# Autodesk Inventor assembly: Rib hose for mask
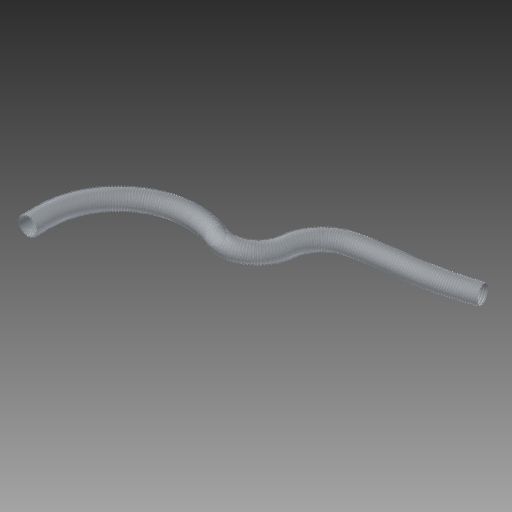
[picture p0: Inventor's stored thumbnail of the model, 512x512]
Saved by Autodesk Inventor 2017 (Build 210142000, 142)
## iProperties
Created: 2020-03
Part Number: Rib hose for mask
Document SubType Name: Assembly
Designer: user
Author: user
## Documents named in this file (3)
- C:\Users\user\Documents\Inventor\Home Ventilator CPAP\Rib hose for mask.iam
- C:\Users\user\Documents\Inventor\Home Ventilator CPAP\hose for mask.ipt
- C:\Users\user\Documents\Inventor\Home Ventilator CPAP\Ring for hose.ipt
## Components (181 placed, 2 different names)
1. hose for mask:1 — Mate:1, Angle:1
2. Ring for hose:1 — Mate:1, Angle:1
3. Ring for hose:2
4. Ring for hose:3
5. Ring for hose:4
6. Ring for hose:5
7. Ring for hose:6
8. Ring for hose:7
9. Ring for hose:8
10. Ring for hose:9
11. Ring for hose:10
12. Ring for hose:11
13. Ring for hose:12
14. Ring for hose:13
15. Ring for hose:14
16. Ring for hose:15
17. Ring for hose:16
18. Ring for hose:17
19. Ring for hose:18
20. Ring for hose:19
21. Ring for hose:20
22. Ring for hose:21
23. Ring for hose:22
24. Ring for hose:23
25. Ring for hose:24
26. Ring for hose:25
27. Ring for hose:26
28. Ring for hose:27
29. Ring for hose:28
30. Ring for hose:29
31. Ring for hose:30
32. Ring for hose:31
33. Ring for hose:32
34. Ring for hose:33
35. Ring for hose:34
36. Ring for hose:35
37. Ring for hose:36
38. Ring for hose:37
39. Ring for hose:38
40. Ring for hose:39
41. Ring for hose:40
42. Ring for hose:41
43. Ring for hose:42
44. Ring for hose:43
45. Ring for hose:44
46. Ring for hose:45
47. Ring for hose:46
48. Ring for hose:47
49. Ring for hose:48
50. Ring for hose:49
51. Ring for hose:50
52. Ring for hose:51
53. Ring for hose:52
54. Ring for hose:53
55. Ring for hose:54
56. Ring for hose:55
57. Ring for hose:56
58. Ring for hose:57
59. Ring for hose:58
60. Ring for hose:59
61. Ring for hose:60
62. Ring for hose:61
63. Ring for hose:62
64. Ring for hose:63
65. Ring for hose:64
66. Ring for hose:65
67. Ring for hose:66
68. Ring for hose:67
69. Ring for hose:68
70. Ring for hose:69
71. Ring for hose:70
72. Ring for hose:71
73. Ring for hose:72
74. Ring for hose:73
75. Ring for hose:74
76. Ring for hose:75
77. Ring for hose:76
78. Ring for hose:77
79. Ring for hose:78
80. Ring for hose:79
81. Ring for hose:80
82. Ring for hose:81
83. Ring for hose:82
84. Ring for hose:83
85. Ring for hose:84
86. Ring for hose:85
87. Ring for hose:86
88. Ring for hose:87
89. Ring for hose:88
90. Ring for hose:89
91. Ring for hose:90
92. Ring for hose:91
93. Ring for hose:92
94. Ring for hose:93
95. Ring for hose:94
96. Ring for hose:95
97. Ring for hose:96
98. Ring for hose:97
99. Ring for hose:98
100. Ring for hose:99
101. Ring for hose:100
102. Ring for hose:101
103. Ring for hose:102
104. Ring for hose:103
105. Ring for hose:104
106. Ring for hose:105
107. Ring for hose:106
108. Ring for hose:107
109. Ring for hose:108
110. Ring for hose:109
111. Ring for hose:110
112. Ring for hose:111
113. Ring for hose:112
114. Ring for hose:113
115. Ring for hose:114
116. Ring for hose:115
117. Ring for hose:116
118. Ring for hose:117
119. Ring for hose:118
120. Ring for hose:119
121. Ring for hose:120
122. Ring for hose:121
123. Ring for hose:122
124. Ring for hose:123
125. Ring for hose:124
126. Ring for hose:125
127. Ring for hose:126
128. Ring for hose:127
129. Ring for hose:128
130. Ring for hose:129
131. Ring for hose:130
132. Ring for hose:131
133. Ring for hose:132
134. Ring for hose:133
135. Ring for hose:134
136. Ring for hose:135
137. Ring for hose:136
138. Ring for hose:137
139. Ring for hose:138
140. Ring for hose:139
141. Ring for hose:140
142. Ring for hose:141
143. Ring for hose:142
144. Ring for hose:143
145. Ring for hose:144
146. Ring for hose:145
147. Ring for hose:146
148. Ring for hose:147
149. Ring for hose:148
150. Ring for hose:149
151. Ring for hose:150
152. Ring for hose:151
153. Ring for hose:152
154. Ring for hose:153
155. Ring for hose:154
156. Ring for hose:155
157. Ring for hose:156
158. Ring for hose:157
159. Ring for hose:158
160. Ring for hose:159
161. Ring for hose:160
162. Ring for hose:161
163. Ring for hose:162
164. Ring for hose:163
165. Ring for hose:164
166. Ring for hose:165
167. Ring for hose:166
168. Ring for hose:167
169. Ring for hose:168
170. Ring for hose:169
171. Ring for hose:170
172. Ring for hose:171
173. Ring for hose:172
174. Ring for hose:173
175. Ring for hose:174
176. Ring for hose:175
177. Ring for hose:176
178. Ring for hose:177
179. Ring for hose:178
180. Ring for hose:179
181. Ring for hose:180
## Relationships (2: Mate 1, Angle 1)
- Mate:1: hose for mask:1 ↔ Ring for hose:1
- Angle:1: hose for mask:1 ↔ Ring for hose:1
